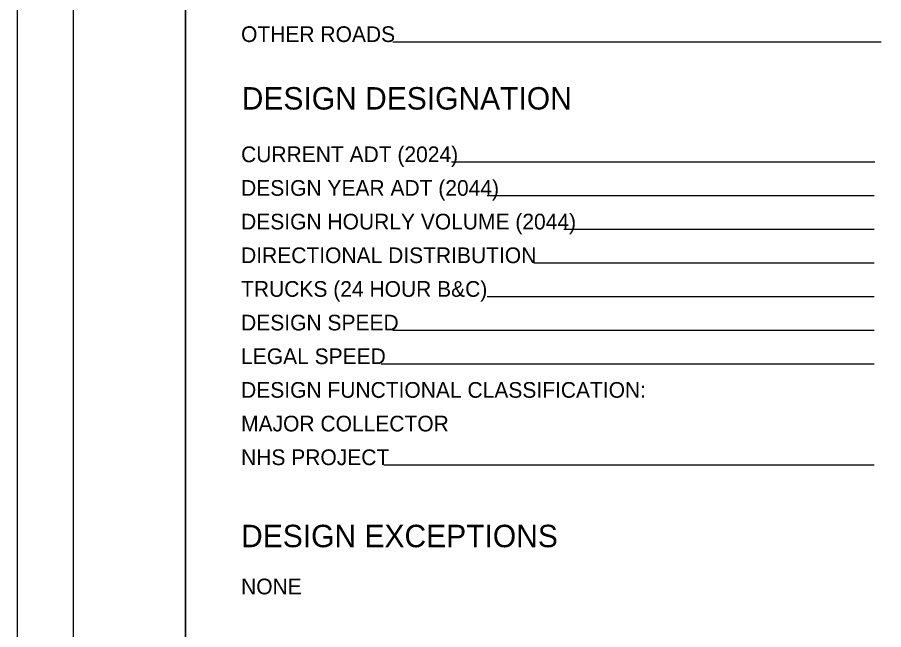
# Model space of a CAD drawing. Extents: x 0 to 34, y 0 to 22.
# Drawn here: x 0 to 7.72, y 5.64 to 11.1 of the extents above; entities that cross this region are included whole.
import ezdxf

# ---------------------------------------------------------------- set-up
doc = ezdxf.new("R2010")
doc.units = 0
for name, color, linetype in [('SH_Border', 7, 'Continuous'), ('SH_Cut_Line', 7, 'Continuous'), ('SH_Data', 7, 'Continuous'), ('SH_Text', 7, 'Continuous')]:
    doc.layers.add(name, color=color, linetype=linetype)

msp = doc.modelspace()

# ---------------------------------------------------------------- linework, layer by layer
at = {"layer": 'SH_Border'}
for points in [[(0.5, 21.5), (1.5, 21.5), (1.5, 0.5), (0.5, 0.5)], [(1.5, 21.5), (33.5, 21.5), (33.5, 0.5), (1.5, 0.5)]]:
    msp.add_lwpolyline(points, close=True, dxfattribs=at)
at = {"layer": 'SH_Cut_Line'}
msp.add_lwpolyline([(0, 0), (34, 0), (34, 22), (0, 22)], close=True, dxfattribs=at)
at = {"layer": 'SH_Data'}
for p, q in [((7.7, 10.8767), (3.3471, 10.8767)), ((7.6424, 9.8062), (3.871, 9.8062)), ((7.6368, 9.5062), (4.1885, 9.5062)), ((7.6368, 9.2062), (4.8723, 9.2062)), ((7.6368, 8.9062), (4.6037, 8.9062)), ((7.6368, 8.6062), (4.1885, 8.6062)), ((7.6368, 8.3062), (3.346, 8.3062)), ((7.6368, 8.0062), (3.2422, 8.0062)), ((7.6368, 7.1062), (3.2669, 7.1062))]:
    msp.add_line(p, q, dxfattribs=at)

# ---------------------------------------------------------------- texts
msp.add_text('DESIGN DESIGNATION', height=0.2, dxfattribs=at).set_placement((2, 10.2747))
at = {"layer": 'SH_Text'}
for s, height, p in [('OTHER ROADS', 0.14, (1.9944, 10.8767)), ('CURRENT ADT (2024)', 0.14, (1.9944, 9.8062)), ('DESIGN YEAR ADT (2044)', 0.14, (1.9944, 9.5062)), ('DESIGN HOURLY VOLUME (2044)', 0.14, (1.9944, 9.2062)), ('DIRECTIONAL DISTRIBUTION', 0.14, (1.9944, 8.9062)), ('TRUCKS (24 HOUR B&C)', 0.14, (1.9944, 8.6062)), ('DESIGN SPEED', 0.14, (1.9944, 8.3062)), ('LEGAL SPEED', 0.14, (1.9944, 8.0062)), ('DESIGN FUNCTIONAL CLASSIFICATION:', 0.14, (1.9944, 7.7062)), ('MAJOR COLLECTOR', 0.14, (1.9944, 7.4062)), ('NHS PROJECT', 0.14, (1.9944, 7.1062)), ('DESIGN EXCEPTIONS', 0.2, (1.9944, 6.3744)), ('NONE', 0.14, (1.9944, 5.9544))]:
    msp.add_text(s, height=height, dxfattribs=at).set_placement(p)

doc.saveas('drawing.dxf')
